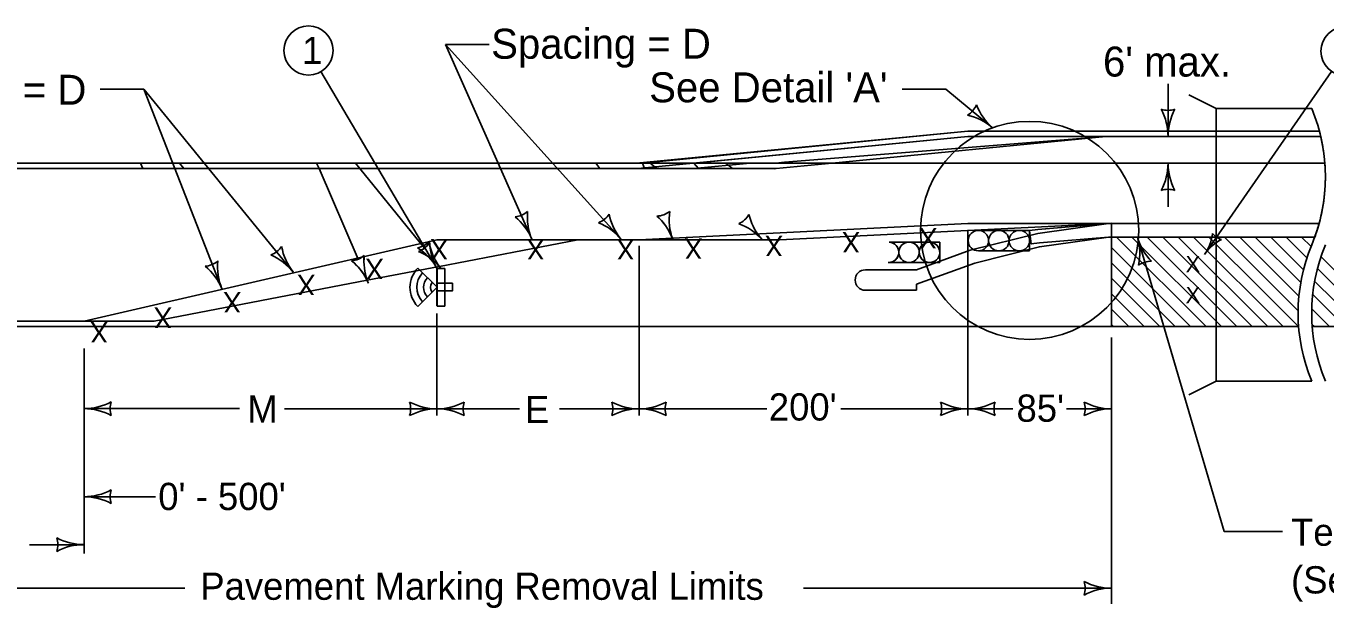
# Model space of a CAD drawing. Extents: x 10133 to 2270741, y 5363 to 1733450.
# Drawn here: x 29731 to 30684, y 6469 to 6896 of the extents above; entities that cross this region are included whole.
import ezdxf

# ---------------------------------------------------------------- set-up
doc = ezdxf.new("R2010")
doc.units = 0
for name, color, linetype in [('dsnNonPlotable', 7, 'Continuous'), ('dsnShtPlotShapeBatchPrint', 7, 'Continuous'), ('dsnStdBlockModified', 7, 'Continuous'), ('dsnStdBorder', 7, 'Continuous'), ('dsnStdNote', 7, 'Continuous'), ('Level 12', 7, 'Continuous'), ('Level 2', 7, 'Continuous')]:
    doc.layers.add(name, color=color, linetype=linetype)

# ---------------------------------------------------------------- blocks, each defined once
blk = doc.blocks.new('LT')
at = {"layer": 'dsnStdBorder'}
for centre, radius, start, end in [((-3.56, 0), 1.64, 342.2666, 17.7333), ((0, 4.25), 4.25, 241.9275, 270), ((0, -4.25), 4.25, 90, 118.0725)]:
    blk.add_arc(centre, radius, start, end, dxfattribs=at)

msp = doc.modelspace()

# ---------------------------------------------------------------- linework, layer by layer
at = {"layer": 'dsnNonPlotable'}
for p, q in [((30604.24, 6835.83), (30584.24, 6845.83)), ((30180.37, 6791.83), (30422.04, 6815.33)), ((30422.04, 6815.33), (30680.85, 6815.33)), ((30523.27, 6815.33), (30680.88, 6815.33)), ((30183.54, 6795.82), (30506.21, 6795.82)), ((30506.21, 6795.82), (30683.86, 6795.82)), ((30180.99, 6739.56), (30422.04, 6751.56)), ((30422.04, 6751.56), (30525.35, 6751.56)), ((30679.65, 6751.56), (30653.3, 6751.56)), ((29774.05, 6679.83), (30032.8, 6739.56)), ((30032.8, 6739.56), (30180.99, 6739.56)), ((30650.13, 6741.56), (30676.48, 6741.56)), ((28158.76, 6679.83), (29774.05, 6679.83)), ((30604.24, 6635.83), (30584.24, 6625.83))]:
    msp.add_line(p, q, dxfattribs=at)
for points in [[(30674.24, 6635.83), (30604.24, 6635.83), (30604.24, 6835.83), (30674.24, 6835.83)], [(28150.78, 6791.83), (30180.37, 6791.83)], [(30467.36, 6746.44), (30473.43, 6747.23), (30525.35, 6751.56)], [(30467.36, 6746.44), (30468.62, 6736.6), (30468.62, 6736.6)], [(30679.65, 6751.56), (30525.35, 6751.56)], [(30468.62, 6736.6), (30474.7, 6737.38), (30525.35, 6741.56)], [(30525.35, 6741.56), (30676.48, 6741.56)]]:
    msp.add_lwpolyline(points, dxfattribs=at)
for centre, start, end in [((30554.24, 6785.82), 337.38013, 22.61986), ((30794.24, 6685.82), 157.38013, 202.61986), ((30804.24, 6685.82), 157.38013, 202.61986)]:
    msp.add_arc(centre, 130, start, end, dxfattribs=at)
at = {"layer": 'dsnShtPlotShapeBatchPrint'}
msp.add_circle((30698.96, 6877.94), 18, dxfattribs=at)
at = {"layer": 'dsnStdBlockModified'}
for p, q in [((30467.36, 6746.44), (30429.85, 6746.44)), ((30467.36, 6731.44), (30467.36, 6746.44)), ((30429.85, 6731.44), (30467.36, 6731.44)), ((30018.76, 6718.84), (30032.9, 6704.69)), ((30038.52, 6718.44), (30032.9, 6718.44)), ((30032.9, 6704.69), (30018.76, 6690.55)), ((30038.52, 6690.94), (30032.9, 6690.94))]:
    msp.add_line(p, q, dxfattribs=at)
for centre in [(30429.85, 6738.94), (30429.85, 6738.94), (30444.85, 6738.94), (30444.85, 6738.94), (30459.86, 6738.94), (30459.86, 6738.94)]:
    msp.add_circle(centre, 7.5, dxfattribs=at)
for radius, start, end in [(20.32, 135.88004, 224.03126), (15.33, 136.16647, 223.71595), (10.34, 136.72938, 223.09626), (5.32, 138.70055, 221.29945)]:
    msp.add_arc((30033.36, 6704.67), radius, start, end, dxfattribs=at)
at = {"layer": 'dsnStdBorder'}
for p, q in [((30527.31, 6675.83), (30527.31, 6741.56)), ((30531.01, 6741.56), (30596.75, 6675.83)), ((30542.33, 6741.56), (30608.06, 6675.83)), ((30553.64, 6741.56), (30619.38, 6675.83)), ((30564.96, 6741.56), (30630.69, 6675.83)), ((30576.27, 6741.56), (30642, 6675.83)), ((30587.58, 6741.56), (30653.32, 6675.83)), ((30598.9, 6741.56), (30638.86, 6701.59)), ((30610.21, 6741.56), (30664.25, 6687.51)), ((30621.52, 6741.56), (30664.84, 6698.24)), ((30632.84, 6741.56), (30666.19, 6708.21)), ((30644.15, 6741.56), (30668.17, 6717.53)), ((30655.47, 6741.56), (30670.71, 6726.31)), ((30666.78, 6741.56), (30673.74, 6734.6)), ((30527.31, 6733.95), (30585.43, 6675.83)), ((30681.04, 6727.3), (30732.51, 6675.83)), ((30032.8, 6691.17), (30032.8, 6718.67)), ((30038.52, 6718.44), (30038.52, 6690.94)), ((30527.31, 6722.64), (30574.12, 6675.83)), ((30678.44, 6718.58), (30721.2, 6675.83)), ((30527.31, 6711.32), (30562.81, 6675.83)), ((30676.39, 6709.32), (30709.89, 6675.83)), ((30527.31, 6700.01), (30551.49, 6675.83)), ((30638.86, 6701.59), (30664.63, 6675.83)), ((30674.96, 6699.44), (30698.57, 6675.83)), ((30527.31, 6688.7), (30540.18, 6675.83)), ((30674.28, 6688.8), (30687.26, 6675.83)), ((30527.31, 6677.38), (30528.87, 6675.83)), ((30638.08, 6679.79), (30642.04, 6675.83)), ((30674.53, 6677.24), (30675.94, 6675.83))]:
    msp.add_line(p, q, dxfattribs=at)
for points in [[(30032.9, 6690.94), (30032.9, 6718.44), (30038.52, 6718.44), (30038.52, 6690.94)], [(30032.9, 6707.62), (30032.9, 6702), (30038.52, 6702), (30038.52, 6707.62)], [(30038.52, 6702), (30038.52, 6707.62), (30044.15, 6707.62), (30044.15, 6702)]]:
    msp.add_lwpolyline(points, close=True, dxfattribs=at)
for centre, radius in [((30467.36, 6746.44), 80), ((30429.85, 6738.94), 7.5), ((30444.85, 6738.94), 7.5), ((30459.86, 6738.94), 7.5)]:
    msp.add_circle(centre, radius, dxfattribs=at)
at = {"layer": 'dsnStdNote'}
msp.add_circle((29938.62, 6878.5), 18, dxfattribs=at)
at = {"layer": 'Level 12'}
for p, q in [((30039.17, 6882.92), (30071.17, 6882.92)), ((30102.39, 6739.91), (30039.17, 6882.92)), ((30167.94, 6739.91), (30039.17, 6882.92)), ((30032.8, 6718.67), (29947.76, 6862.99)), ((30595.66, 6728.83), (30688.68, 6863.16)), ((29785.81, 6850.05), (29817.81, 6850.05)), ((29927.49, 6715.93), (29817.81, 6850.05)), ((29875.21, 6703.62), (29817.81, 6850.05)), ((30373.99, 6850.05), (30405.99, 6850.05)), ((30440.27, 6821.72), (30405.99, 6850.05)), ((30568.89, 6854.09), (30568.89, 6815.33)), ((30559.08, 6815.33), (30576.89, 6815.33)), ((30558.07, 6795.82), (30576.89, 6795.82)), ((30568.89, 6763.82), (30568.89, 6795.82)), ((30422.04, 6746.71), (30422.04, 6610.59)), ((30180.99, 6735.13), (30180.99, 6610.59)), ((30546.39, 6741.56), (30609.92, 6525.54)), ((30032.8, 6685.44), (30032.8, 6610.59)), ((30527.31, 6667.83), (30527.31, 6472.46)), ((29774.05, 6659.86), (29774.05, 6509.44)), ((29888.02, 6615.65), (29774.05, 6615.65)), ((30034.54, 6615.5), (29921.09, 6615.5)), ((29977.21, 6615.5), (30093.46, 6615.5)), ((30274.8, 6615.5), (30122.6, 6615.5)), ((30422.1, 6615.5), (30328.96, 6615.5)), ((30455.1, 6615.5), (30422.1, 6615.5)), ((30527.37, 6615.5), (30494.37, 6615.5)), ((29826.51, 6551.01), (29774.05, 6551.01)), ((30652.76, 6525.54), (30609.92, 6525.54)), ((29734.05, 6515.75), (29774.05, 6515.75)), ((29847.94, 6483.87), (29640.25, 6483.87)), ((30301.62, 6483.87), (30527.31, 6483.87))]:
    msp.add_line(p, q, dxfattribs=at)
for centre, radius, start, end in [((30413.4, 6845.12), 16.42, 301.22013, 336.68683), ((30412.36, 6789.66), 42.5, 48.95348, 77.02597), ((30468.18, 6853.77), 42.5, 200.88099, 228.95348), ((30568.89, 6850.96), 16.42, 252.26665, 287.73335), ((30526.39, 6815.33), 42.5, 0, 28.07249), ((30611.39, 6815.33), 42.5, 151.92751, 180), ((30526.39, 6795.82), 42.5, 331.92751, 0), ((30611.39, 6795.82), 42.5, 180, 208.07249), ((30568.89, 6760.19), 16.42, 72.26665, 107.73335), ((30088.68, 6772.8), 16.42, 274.89451, 310.36122), ((30063.16, 6723.56), 42.5, 22.62786, 50.70035), ((30141.62, 6756.26), 42.5, 174.55538, 202.62786), ((30145.3, 6767.39), 16.42, 291.6303, 327.097), ((30200.76, 6766.79), 42.5, 191.29116, 219.36365), ((30135.05, 6712.88), 42.5, 39.36365, 67.43614), ((29905.26, 6743.78), 16.42, 290.85489, 326.32159), ((29960.71, 6742.44), 42.5, 190.51575, 218.58824), ((30015.37, 6749.75), 16.42, 281.55535, 317.02205), ((30069.87, 6739.46), 42.5, 181.21621, 209.2887), ((30505.62, 6729.57), 42.5, 348.31445, 16.38694), ((30587.17, 6753.55), 42.5, 196.38694, 224.45943), ((29894.27, 6689.42), 42.5, 38.58824, 66.66073), ((29995.74, 6697.88), 42.5, 29.2887, 57.36119), ((29861.48, 6736.51), 16.42, 274.92867, 310.39537), ((29835.99, 6687.25), 42.5, 22.66202, 50.73451), ((29914.43, 6720), 42.5, 174.58953, 202.66202), ((30556.45, 6707.37), 16.42, 88.65359, 124.12029), ((29774.05, 6658.15), 42.5, 270, 298.07249), ((29809.69, 6615.65), 16.42, 162.26665, 197.73335), ((29997.17, 6615.5), 16.42, 342.26665, 17.73335), ((30032.8, 6658), 42.5, 241.92751, 270), ((30032.8, 6658), 42.5, 270, 298.07249), ((30068.44, 6615.5), 16.42, 162.26665, 197.73335), ((30145.35, 6615.5), 16.42, 342.26665, 17.73335), ((30180.99, 6658), 42.5, 241.92751, 270), ((30180.99, 6658), 42.5, 270, 298.07249), ((30216.62, 6615.5), 16.42, 162.26665, 197.73335), ((30386.46, 6615.5), 16.42, 342.26665, 17.73335), ((30422.1, 6658), 42.5, 241.92751, 270), ((30422.1, 6658), 42.5, 270, 298.07249), ((30457.74, 6615.5), 16.42, 162.26665, 197.73335), ((30491.73, 6615.5), 16.42, 342.26665, 17.73335), ((30527.37, 6658), 42.5, 241.92751, 270), ((29774.05, 6573.15), 42.5, 61.92751, 90), ((30032.8, 6573), 42.5, 90, 118.07249), ((30032.8, 6573), 42.5, 61.92751, 90), ((30180.99, 6573), 42.5, 90, 118.07249), ((30180.99, 6573), 42.5, 61.92751, 90), ((30422.1, 6573), 42.5, 90, 118.07249), ((30422.1, 6573), 42.5, 61.92751, 90), ((30527.37, 6573), 42.5, 90, 118.07249), ((29774.05, 6593.51), 42.5, 270, 298.07249), ((29809.69, 6551.01), 16.42, 162.26665, 197.73335), ((29774.05, 6508.51), 42.5, 61.92751, 90), ((29738.42, 6515.89), 16.42, 342.26665, 17.73335), ((29774.05, 6558.39), 42.5, 241.92751, 270), ((29774.05, 6473.39), 42.5, 90, 118.07249), ((30491.67, 6483.87), 16.42, 342.26665, 17.73335), ((30527.31, 6526.37), 42.5, 241.92751, 270), ((30527.31, 6441.37), 42.5, 90, 118.07249)]:
    msp.add_arc(centre, radius, start, end, dxfattribs=at)
at = {"layer": 'Level 2'}
for p, q in [((30179.21, 6795.71), (30422.04, 6819.33)), ((30183.54, 6795.82), (30422.04, 6819.33)), ((30422.04, 6815.33), (30221.49, 6795.82)), ((30221.49, 6795.82), (30422.04, 6815.33)), ((30523.27, 6815.33), (30287.71, 6796.44)), ((30322.72, 6795.82), (30523.27, 6815.33)), ((30422.04, 6819.33), (30679.84, 6819.33)), ((30422.04, 6819.33), (30568.7, 6819.33)), ((30568.89, 6815.33), (30422.04, 6815.33)), ((30422.04, 6815.33), (30559.08, 6815.33)), ((30559.08, 6815.33), (30568.89, 6815.33)), ((30576.89, 6815.33), (30568.89, 6815.33)), ((30568.89, 6815.33), (30576.89, 6815.33)), ((30569.08, 6819.33), (30604.24, 6819.33)), ((30604.24, 6815.33), (30576.89, 6815.33)), ((30576.89, 6815.33), (30604.24, 6815.33)), ((30604.24, 6819.33), (30604.24, 6815.33)), ((30604.24, 6819.33), (30604.24, 6815.33)), ((30680.85, 6815.33), (30604.24, 6815.33)), ((30604.24, 6815.33), (30604.24, 6795.82)), ((30604.24, 6815.33), (30604.24, 6795.82)), ((30604.24, 6815.33), (30680.85, 6815.33)), ((30653.51, 6819.33), (30679.91, 6819.33)), ((28150.78, 6791.83), (29946.34, 6791.83)), ((29944.62, 6795.82), (28154.78, 6795.83)), ((28154.78, 6795.82), (30281.4, 6795.82)), ((29946.34, 6791.83), (29368.02, 6791.83)), ((29815.48, 6795.82), (29844.03, 6795.82)), ((29817.1, 6791.83), (29815.48, 6795.82)), ((29847.16, 6791.83), (29817.1, 6791.83)), ((29844.03, 6795.82), (29847.16, 6791.83)), ((29973.11, 6795.82), (29944.62, 6795.82)), ((29944.62, 6795.82), (29946.34, 6791.83)), ((29946.34, 6791.83), (29944.62, 6795.82)), ((29946.34, 6791.83), (29976.35, 6791.83)), ((29974.98, 6725.31), (29946.34, 6791.83)), ((29976.35, 6791.83), (29946.34, 6791.83)), ((29946.34, 6791.83), (29974.98, 6725.31)), ((30183.54, 6795.82), (29973.11, 6795.82)), ((29973.11, 6795.82), (29976.35, 6791.83)), ((29976.35, 6791.83), (29973.11, 6795.82)), ((29976.35, 6791.83), (30185.13, 6791.83)), ((30185.13, 6791.83), (29976.35, 6791.83)), ((29976.35, 6791.83), (30023.62, 6733.48)), ((30023.62, 6733.48), (29976.35, 6791.83)), ((30152.28, 6791.83), (30149.35, 6795.82)), ((30149.35, 6795.82), (30189.09, 6795.82)), ((30194.14, 6791.83), (30152.28, 6791.83)), ((30185.13, 6791.83), (30183.54, 6795.82)), ((30221.49, 6795.82), (30183.54, 6795.82)), ((30244.59, 6795.82), (30183.54, 6795.82)), ((30183.54, 6795.82), (30185.13, 6791.83)), ((30185.13, 6791.83), (30249.43, 6791.83)), ((30224.69, 6791.83), (30185.13, 6791.83)), ((30189.09, 6795.82), (30194.14, 6791.83)), ((30194.14, 6791.83), (30189.09, 6795.82)), ((30189.09, 6795.82), (30220.65, 6795.82)), ((30221.23, 6791.83), (30194.14, 6791.83)), ((30220.65, 6795.82), (30262.51, 6795.82)), ((30221.1, 6795.82), (30224.69, 6791.83)), ((30262.51, 6795.82), (30221.23, 6791.83)), ((30506.21, 6795.82), (30221.49, 6795.82)), ((30249.43, 6791.83), (30244.59, 6795.82)), ((30287.71, 6796.44), (30281.4, 6795.82)), ((30281.4, 6795.82), (30322.72, 6795.82)), ((30281.6, 6791.83), (30322.72, 6795.82)), ((30506.21, 6795.82), (30322.72, 6795.82)), ((30558.07, 6795.82), (30506.21, 6795.82)), ((30568.89, 6795.82), (30558.07, 6795.82)), ((30568.89, 6776.6), (30568.89, 6795.82)), ((30604.24, 6795.82), (30683.86, 6795.82)), ((30683.86, 6795.82), (30604.24, 6795.82)), ((30604.24, 6795.82), (30604.24, 6751.56)), ((30604.24, 6751.56), (30604.24, 6795.82)), ((30525.35, 6751.56), (30284.29, 6739.56)), ((30284.29, 6739.56), (30525.35, 6751.56)), ((30468.62, 6736.6), (30467.36, 6746.44)), ((30527.31, 6751.66), (30525.35, 6751.56)), ((30525.35, 6751.56), (30679.65, 6751.56)), ((30525.35, 6751.56), (30604.24, 6751.56)), ((30527.31, 6741.56), (30527.31, 6751.66)), ((30604.24, 6751.56), (30679.65, 6751.56)), ((30136.11, 6739.56), (30034.58, 6720.04)), ((30034.58, 6720.04), (30136.11, 6739.56)), ((30251.5, 6739.56), (30136.11, 6739.56)), ((30136.11, 6739.56), (30284.29, 6739.56)), ((30204.9, 6741.93), (30205.7, 6739.9)), ((30284.29, 6739.56), (30251.5, 6739.56)), ((30251.75, 6739.22), (30251.5, 6739.56)), ((30269.57, 6741.77), (30271.24, 6739.91)), ((30271.25, 6739.9), (30269.58, 6741.76)), ((30364.37, 6737.89), (30378.94, 6737.89)), ((30379.38, 6737.89), (30394.38, 6737.89)), ((30394.38, 6737.89), (30401.49, 6737.89)), ((30401.49, 6737.89), (30401.49, 6730.39)), ((30676.48, 6741.56), (30525.35, 6741.56)), ((30527.31, 6675.83), (30527.31, 6741.56)), ((30401.49, 6729.99), (30401.49, 6722.88)), ((30034.49, 6720.02), (29981.73, 6709.88)), ((29981.73, 6709.88), (30034.49, 6720.02)), ((30035.72, 6718.55), (30035.32, 6719.04)), ((30346.95, 6717.55), (30384.47, 6717.55)), ((30384.47, 6717.55), (30346.95, 6717.55)), ((30378.59, 6722.88), (30363.98, 6722.88)), ((30393.6, 6722.88), (30378.59, 6722.88)), ((30401.49, 6722.88), (30393.6, 6722.88)), ((29825.43, 6679.83), (29981.59, 6709.85)), ((29981.59, 6709.85), (29825.43, 6679.83)), ((30384.47, 6702.54), (30384.47, 6706.91)), ((30384.47, 6702.54), (30346.95, 6702.54)), ((30346.95, 6702.54), (30384.47, 6702.54)), ((29584.52, 6679.83), (29825.43, 6679.83)), ((29825.43, 6679.83), (29584.52, 6679.83)), ((28154.78, 6675.83), (30486.98, 6675.83)), ((29584.52, 6675.83), (30415.17, 6675.83)), ((30415.17, 6675.83), (30664.63, 6675.83)), ((30845.01, 6675.83), (30674.63, 6675.83))]:
    msp.add_line(p, q, dxfattribs=at)
for points in [[(30679.84, 6819.33), (30653.51, 6819.33), (30604.24, 6819.33)], [(30679.85, 6819.33), (30679.84, 6819.33)], [(30322.72, 6795.82), (30281.4, 6795.82), (30221.1, 6795.82)], [(30224.69, 6791.83), (30280.64, 6791.83), (30281.6, 6791.83)], [(30280.64, 6791.83), (30276.33, 6791.83), (30224.69, 6791.83)], [(30322.72, 6795.82), (30281.6, 6791.83), (30280.64, 6791.73)], [(30280.64, 6791.73), (30280.64, 6791.83)], [(30604.24, 6795.82), (30576.89, 6795.82), (30568.89, 6795.82), (30558.07, 6795.82), (30506.21, 6795.82)], [(30604.24, 6795.82), (30576.89, 6795.82), (30568.89, 6795.82)], [(30384.47, 6717.55), (30423.9, 6731.9), (30473.42, 6744.3), (30525.35, 6751.56)], [(30525.35, 6751.56), (30473.42, 6744.3), (30423.9, 6731.9), (30384.47, 6717.55)], [(30467.36, 6746.44), (30473.43, 6747.23), (30525, 6751.53), (30525.35, 6751.56)], [(30525.35, 6751.56), (30525.35, 6751.56)], [(30205.7, 6739.91), (30205.7, 6739.91), (30204.89, 6741.94)], [(30205.7, 6739.9), (30205.7, 6739.91)], [(30271.24, 6739.91), (30271.21, 6739.84)], [(30271.21, 6739.84), (30271.25, 6739.9)], [(30364.37, 6737.88), (30364.37, 6737.89)], [(30379.38, 6737.88), (30379.38, 6737.89)], [(30527.31, 6741.56), (30525.35, 6741.56), (30474.6, 6734.43), (30427.32, 6722.51), (30384.47, 6706.91)], [(30384.47, 6706.91), (30427.32, 6722.51), (30474.6, 6734.43), (30525.35, 6741.56), (30527.31, 6741.56)], [(30394.38, 6737.88), (30394.38, 6737.89)], [(30394.38, 6737.89), (30394.38, 6737.88)], [(30525.35, 6741.56), (30474.7, 6737.38), (30468.62, 6736.6)], [(30371.47, 6729.99), (30371.49, 6729.99)], [(30386.48, 6729.99), (30386.5, 6729.99)], [(30401.48, 6729.99), (30401.49, 6729.99)], [(30034.49, 6720.01), (30034.59, 6720.03)], [(30378.59, 6722.89), (30378.59, 6722.88)], [(30378.59, 6722.88), (30378.59, 6722.89)], [(30393.6, 6722.89), (30393.6, 6722.88)], [(30393.6, 6722.88), (30393.6, 6722.89)], [(29982.58, 6707.66), (29982.58, 6707.66), (29982.21, 6708.52)], [(29982.22, 6708.51), (29982.24, 6708.52)], [(30384.47, 6706.91), (30384.47, 6706.91), (30384.47, 6702.54)], [(30415.17, 6675.83), (30486.98, 6675.83), (30527.31, 6675.83)]]:
    msp.add_lwpolyline(points, dxfattribs=at)
for centre, radius, start, end in [((30526.39, 6815.33), 42.5, 0, 5.40055), ((30611.39, 6815.33), 42.5, 174.59945, 179.9824), ((30526.39, 6815.33), 42.5, 0, 0.0176), ((30554.24, 6785.82), 130, 13.11835, 14.93711), ((30554.24, 6785.82), 130, 4.41173, 13.11835), ((30526.39, 6795.82), 42.5, 331.92751, 0), ((30554.24, 6785.82), 130, 344.71769, 4.41173), ((30568.89, 6760.19), 16.42, 90, 107.73335), ((30193.43, 6773.37), 16.42, 272.4117, 307.87841), ((30193.43, 6773.35), 16.42, 272.4117, 307.87841), ((30165.8, 6725.27), 42.5, 23.08987, 48.21754), ((30165.8, 6725.26), 42.5, 23.08987, 48.21754), ((30245.6, 6754.55), 42.5, 172.07256, 200.12745), ((30245.6, 6754.54), 42.5, 172.07256, 200.12745), ((30247.38, 6766.34), 16.42, 294.23038, 329.69708), ((30247.39, 6766.32), 16.42, 294.23038, 329.69708), ((30302.81, 6768.26), 42.5, 193.89124, 218.54149), ((30302.82, 6768.24), 42.5, 193.89124, 218.54149), ((30239.61, 6711.42), 42.5, 41.98133, 70.03621), ((30239.62, 6711.41), 42.5, 41.98133, 70.03621), ((30554.24, 6785.82), 130, 340.09277, 344.71769), ((30013.5, 6746.39), 16.42, 290.85489, 326.32159), ((30013.49, 6746.4), 16.42, 308.09045, 326.32159), ((30068.94, 6745.05), 42.5, 190.51575, 216.05847), ((30068.94, 6745.04), 42.5, 190.51575, 216.05847), ((30165.8, 6725.27), 42.5, 20.14505, 20.16266), ((30286.09, 6764.26), 42.5, 215.53894, 216.08181), ((30217.41, 6714.18), 42.5, 36.09942, 36.11702), ((30286.09, 6764.26), 42.5, 216.09886, 216.09942), ((30302.81, 6768.26), 42.5, 221.94612, 221.96373), ((30363.96, 6730.34), 7.55, 3.31891, 86.85969), ((30363.98, 6730.39), 7.5, 42.02925, 86.99754), ((30363.96, 6730.34), 7.55, 3.33369, 42.17238), ((30378.99, 6730.39), 7.5, 267, 266.95518), ((30378.99, 6730.39), 7.5, 90.32252, 176.98686), ((30378.96, 6730.34), 7.55, 3.32299, 86.85561), ((30378.99, 6730.39), 7.5, 40.94586, 87.00017), ((30378.96, 6730.34), 7.55, 3.4004, 41.09796), ((30393.99, 6730.39), 7.5, 86.99578, 177.00422), ((30393.99, 6730.39), 7.5, 86.99754, 176.91872), ((30393.99, 6730.39), 7.5, 356.99981, 87.00019), ((30393.99, 6730.39), 7.5, 0, 86.99754), ((29968.85, 6740.54), 16.42, 274.92867, 291.92077), ((29968.86, 6740.53), 16.42, 274.92867, 310.39537), ((29968.85, 6740.54), 16.42, 291.92077, 310.39537), ((30021.8, 6724.03), 42.5, 174.58953, 199.4578), ((30021.81, 6724.02), 42.5, 174.58953, 199.4578), ((30013.49, 6746.4), 16.42, 290.85489, 308.09045), ((30002.5, 6692.04), 42.5, 41.17812, 66.66073), ((30002.5, 6692.03), 42.5, 41.17812, 66.66073), ((30363.98, 6730.39), 7.5, 267.00007, 356.99993), ((30363.98, 6730.39), 7.5, 270, 357.00426), ((30378.99, 6730.39), 7.5, 182.98758, 266.95828), ((30378.99, 6730.39), 7.5, 267.0031, 357.00426), ((30393.99, 6730.39), 7.5, 177.00604, 266.99396), ((30393.99, 6730.39), 7.5, 182.98758, 267.0031), ((30393.98, 6730.4), 7.51, 267.1005, 356.8995), ((30393.99, 6730.39), 7.5, 267.0031, 357.00407), ((29943.36, 6691.28), 42.5, 25.9041, 50.73451), ((29943.37, 6691.27), 42.5, 23.92804, 50.73451), ((30002.5, 6692.04), 42.5, 39.43851, 41.17812), ((30068.94, 6745.05), 42.5, 216.05847, 218.57064), ((30002.5, 6692.04), 42.5, 38.58824, 38.60584), ((30068.94, 6745.05), 42.5, 218.58751, 218.58824), ((30346.95, 6710.05), 7.5, 90, 270), ((30346.95, 6710.05), 7.5, 90, 270), ((29943.36, 6691.28), 42.5, 23.92804, 25.9041), ((30021.8, 6724.03), 42.5, 199.4578, 202.64442), ((30021.81, 6724.02), 42.5, 199.4578, 201.39662), ((29943.36, 6691.28), 42.5, 22.66202, 22.67962)]:
    msp.add_arc(centre, radius, start, end, dxfattribs=at)

# ---------------------------------------------------------------- block references
at = {"layer": 'Level 12', "xscale": 7.999600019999, "yscale": 7.999200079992, "rotation": -124.70293665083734}
msp.add_blockref('LT', (30595.66, 6728.83), dxfattribs=at)

# ---------------------------------------------------------------- texts
at = {"layer": 'dsnStdBorder'}
for p in [(30343.17, 6745.38), (30399.69, 6748.19), (30041.26, 6740.12), (30111.9, 6740.12), (30177.86, 6740.12), (30227.61, 6740.62), (30286.64, 6742.58), (29993.81, 6725.69), (29943.7, 6713.94), (29889.43, 6701.25), (29838.62, 6689.88), (29791.84, 6679.21)]:
    msp.add_text('X', height=15, rotation=180, dxfattribs=at).set_placement(p)
for p in [(30581.79, 6715.68), (30581.79, 6693.03)]:
    msp.add_text('X', height=12, dxfattribs=at).set_placement(p)
at = {"layer": 'dsnStdNote'}
msp.add_text('1', height=20, dxfattribs=at).set_placement((29933.88, 6868.5))
at = {"layer": 'Level 12'}
for s, height, p in [('Spacing = D', 22, (30072.59, 6872.45)), ("6' max.", 22, (30521.19, 6859.36)), ('Spacing = D', 22, (29614.72, 6838.67)), ("See Detail 'A'", 22, (30188.45, 6840.47)), ('M', 20, (29893.74, 6605.35)), ('E', 20, (30097.4, 6605)), ("200'", 20, (30276.15, 6606.92)), ("85'", 20, (30457.77, 6606.02)), ("0' - 500'", 20, (29828.48, 6541.22)), ('Temporary Barrier Rail', 20, (30659.08, 6515.01)), ('Pavement Marking Removal Limits', 20, (29859.28, 6475.35)), ('(See Typical 8210)', 20, (30659.08, 6480.01))]:
    msp.add_text(s, height=height, dxfattribs=at).set_placement(p)

doc.saveas('drawing.dxf')
